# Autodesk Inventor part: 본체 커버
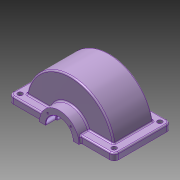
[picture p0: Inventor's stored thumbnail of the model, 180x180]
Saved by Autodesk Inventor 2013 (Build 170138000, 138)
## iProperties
Created: 2023-06
Part Number: 본체 커버
Material: 일반
Document SubType Name: Modeling
Designer: mdu-01
Density: 1 g/cm^3
Author: mdu-01
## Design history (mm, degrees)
sketch "스케치1"
  geometry: L1 (0, 70)-(0, -70); L2 (0, 70)-(45, 70); L3 (45, 70)-(45, 45); L4 (45, 45)-(100, 45); L5 (0, 0)-(100, 0); L6 (0, -70)-(45, -70); L7 (45, -70)-(45, -45); L8 (45, -45)-(100, -45); L9 (100, 45)-(100, -45); 1 further point
  constraints: 18 end point, 3 perpendicular, 3 symmetric about line, 2 midpoint, 2 parallel, 1 coincident, 1 vertical
  dimensions: "d0" = 140 distance of L1.start L1.end; "d1" = 90 diameter of L3 L1; "d2" = 90 distance between parallel lines of L8 L4; "d3" = 200 diameter of L9 L1
revolve "회전1" sketch "스케치1" stored, may be unused: angle "d4" = 180 deg
sketch "스케치2"
  geometry: L1 (-10, -110)-(210, -110); L2 (220, -100)-(220, 10); L3 (210, 20)-(-10, 20); L4 (-20, 10)-(-20, -100); L5 (-20, -110)-(220, 20); L6 (220, -110)-(-20, 20); A1 r 10 centre (-10, 10) between (-10, 20) and (-20, 10); A2 r 10 centre (210, 10) between (220, 10) and (210, 20); A3 r 10 centre (210, -100) between (210, -110) and (220, -100); A4 r 10 centre (-10, -100) between (-20, -100) and (-10, -110); 1 further point
  constraints: 12 end point, 8 point on circle, 8 point on line, 8 tangent, 4 centre point, 3 equal radius, 2 midpoint, 2 parallel, 1 horizontal, 1 perpendicular
  dimensions: "d5" = 240 distance of L6.end L5.end; "d6" = 130 distance of L5.end L6.start; "d7" = 10 radius of A1
extrude "돌출1" join sketch "스케치2" distance "d8" = 15; taper "d9" = 0 deg
sketch "스케치3"
  geometry: L1 (0, 70)-(45, 70) reference; L2 (0, -70)-(45, -70) reference; L3 (0, 70)-(0, -70); L4 (31, 70)-(31, 48); L5 (30, 47)-(27.5, 47); L6 (27.5, 47)-(27.5, 32); L7 (27.5, 32)-(87, 32); L8 (0, 0)-(92.097, 0); L9 (31, -70)-(31, -48); L10 (30, -47)-(27.5, -47); L11 (27.5, -47)-(27.5, -32); L12 (27.5, -32)-(87, -32); L13 (87, 32)-(87, -32); L14 (0, 70)-(31, 70); L15 (0, -70)-(31, -70); A1 r 1 centre (30, 48) between (30, 47) and (31, 48); A2 r 1 centre (30, -48) between (31, -48) and (30, -47); 2 further points
  constraints: 26 end point, 5 point on line, 5 symmetric about line, 4 parallel, 4 point on circle, 4 tangent, 3 perpendicular, 2 centre point, 2 collinear, 1 equal radius
  dimensions: "d10" = 1 radius of A1; "d11" = 62 diameter of L4 L3; "d12" = 23 distance between parallel lines of L1 L5; "d13" = 64 distance between parallel lines of L12 L7; "d14" = 55 diameter of L6 L3; "d15" = 87 distance between parallel lines of L13 L3
revolve "회전2" sketch "스케치3" stored, may be unused: angle "d16" = 180 deg
fillet "모깎기1" dims "d17" = 3
fillet "모깎기2" dims "d18" = 3
sketch "스케치4"
  geometry: L1 (-7, -7)-(207, -7); L2 (207, -7)-(207, 97); L3 (207, 97)-(-7, 97); L4 (-7, 97)-(-7, -7); L5 (-7, -7)-(207, 97); L6 (207, -7)-(-7, 97); 1 further point
  constraints: 12 end point, 2 midpoint, 2 parallel, 1 horizontal, 1 perpendicular
  dimensions: "d19" = 214 distance of L3.end L2.end; "d20" = 104 distance of L2.end L1.end
hole "구멍1" sketch "스케치4" at (207, -7), (-7, -7), (207, 97), (-7, 97) diameter "d21" = 6.6; stored, may be unused: countersink angle "d25" = 90 deg, drill point angle "d27" = 118 deg; dims "d22" = 6, "d23" = 11, "d24" = 6.8, "d26" = 8
sketch "스케치5"
  geometry: L1 (-26.163, 26.163)-(26.163, 26.163); L2 (26.163, 26.163)-(26.163, -26.163); L3 (26.163, -26.163)-(-26.163, -26.163); L4 (-26.163, -26.163)-(-26.163, 26.163); A1 r 37 centre (0, 0) between (-26.163, 26.163) and (26.163, -26.163); 1 further point
  constraints: 8 end point, 3 point on circle, 2 parallel, 2 perpendicular, 1 centre point, 1 coincident, 1 horizontal
  dimensions: "d28" = 74 diameter of A1
hole "구멍2" sketch "스케치5" at (-26.163, 26.163), (26.163, 26.163) diameter "d29" = 4.134; stored, may be unused: countersink angle "d33" = 90 deg, drill point angle "d35" = 118 deg; dims "d30" = 10, "d31" = 11, "d32" = 6.8, "d34" = 12
chamfer "모따기1" distance "d36" = 1; stored, may be unused: second distance "d37" = 2, angle "d38" = 45 deg
node "솔리드1"
mirror "대칭1"
